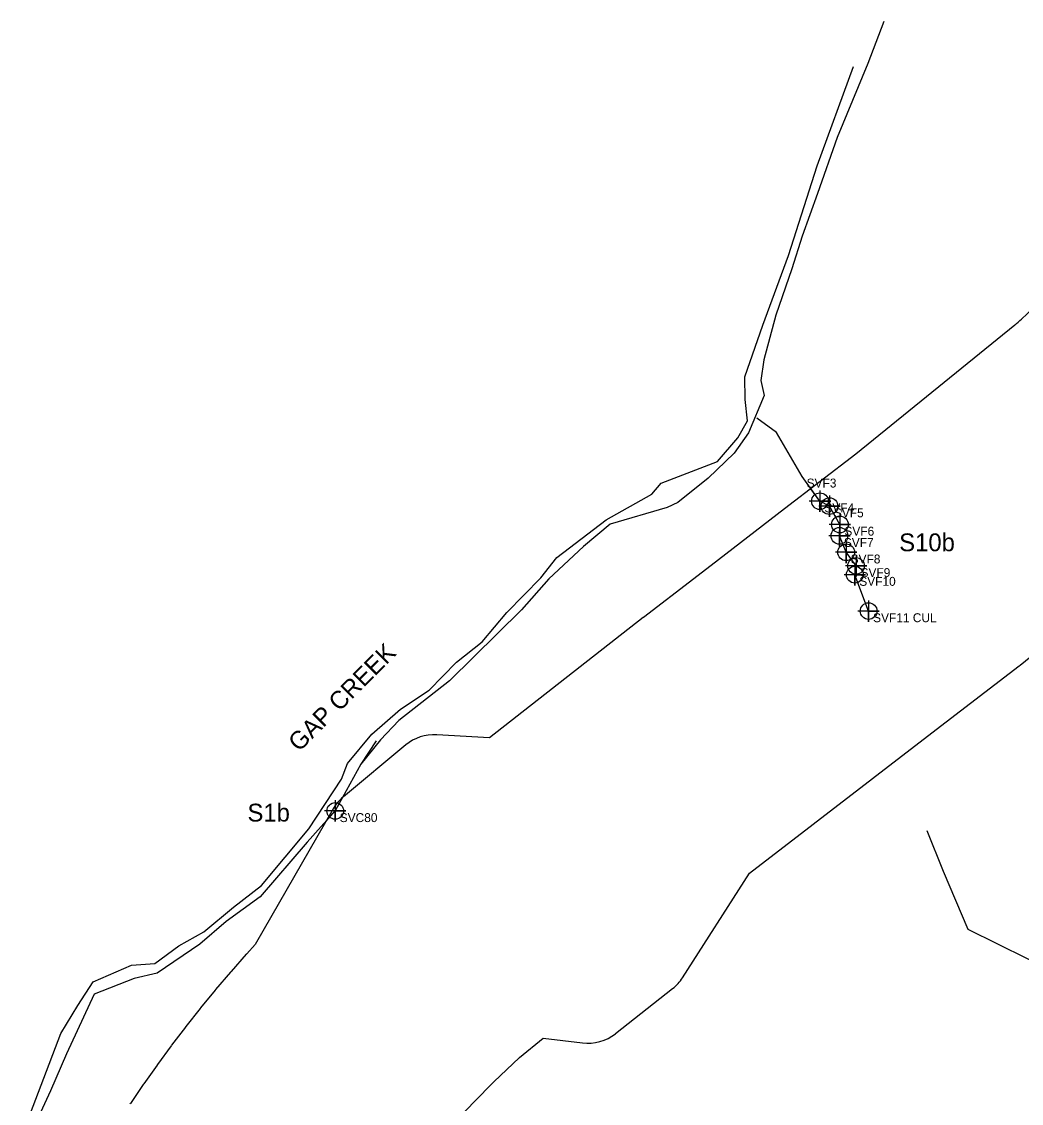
# Model space of a CAD drawing. Extents: x 1253697 to 1278588, y 912189 to 981699.
# Drawn here: x 1260127 to 1261249, y 917399 to 918613 of the extents above; entities that cross this region are included whole.
import ezdxf

# ---------------------------------------------------------------- set-up
doc = ezdxf.new("R2010")
doc.units = 0
for name, color, linetype in [('Default', 7, 'Continuous'), ('Exist Hydro Jurisdictional Stream or Body of Water Mitigable', 7, 'Continuous'), ('Exist Hydro Jurisdictional Stream or Body of Water Mitigable Cogo Comment', 7, 'Continuous'), ('Exist Hydro Jurisdictional Stream or Body of Water Mitigable Cogo Number', 7, 'Continuous'), ('Exist Hydro Jurisdictional Stream or Body of Water Mitigable Cogo Point CELL', 7, 'Continuous')]:
    doc.layers.add(name, color=color, linetype=linetype)

msp = doc.modelspace()

# ---------------------------------------------------------------- linework, layer by layer
at = {"layer": 'Default'}
for p, q in [((1260881.3, 917987.7), (1260824.7, 917944.2)), ((1260881.3, 917987.7), (1260824.7, 917944.2)), ((1260881.3, 917987.7), (1260824.7, 917944.2)), ((1260881.3, 917987.7), (1260824.7, 917944.2)), ((1260558, 917801.1), (1260488, 917743.1)), ((1260558, 917801.1), (1260488, 917743.1)), ((1260558, 917801.1), (1260488, 917743.1)), ((1260558, 917801.1), (1260488, 917743.1)), ((1260379, 917566.3), (1260362, 917547)), ((1260379, 917566.3), (1260362, 917547)), ((1260379, 917566.3), (1260362, 917547)), ((1260379, 917566.3), (1260362, 917547)), ((1260361.4, 917546.3), (1260344.7, 917526.7)), ((1260361.4, 917546.3), (1260344.7, 917526.7)), ((1260361.4, 917546.3), (1260344.7, 917526.7)), ((1260361.4, 917546.3), (1260344.7, 917526.7)), ((1260344.2, 917526), (1260327.8, 917506.1)), ((1260344.2, 917526), (1260327.8, 917506.1)), ((1260344.2, 917526), (1260327.8, 917506.1)), ((1260344.2, 917526), (1260327.8, 917506.1)), ((1260793.4, 917477.2), (1260857.5, 917527.7)), ((1260793.4, 917477.2), (1260857.5, 917527.7)), ((1260793.4, 917477.2), (1260857.5, 917527.7)), ((1260793.4, 917477.2), (1260857.5, 917527.7)), ((1260327.3, 917505.4), (1260311.3, 917485.2)), ((1260327.3, 917505.4), (1260311.3, 917485.2)), ((1260327.3, 917505.4), (1260311.3, 917485.2)), ((1260327.3, 917505.4), (1260311.3, 917485.2)), ((1260310.8, 917484.5), (1260295.2, 917464.1)), ((1260310.8, 917484.5), (1260295.2, 917464.1)), ((1260310.8, 917484.5), (1260295.2, 917464.1)), ((1260310.8, 917484.5), (1260295.2, 917464.1)), ((1260294.6, 917463.4), (1260279.4, 917442.6)), ((1260294.6, 917463.4), (1260279.4, 917442.6)), ((1260294.6, 917463.4), (1260279.4, 917442.6)), ((1260294.6, 917463.4), (1260279.4, 917442.6)), ((1260278.9, 917441.9), (1260264, 917420.9)), ((1260278.9, 917441.9), (1260264, 917420.9)), ((1260278.9, 917441.9), (1260264, 917420.9)), ((1260278.9, 917441.9), (1260264, 917420.9)), ((1260263.5, 917420.2), (1260249, 917399)), ((1260263.5, 917420.2), (1260249, 917399)), ((1260263.5, 917420.2), (1260249, 917399)), ((1260263.5, 917420.2), (1260249, 917399))]:
    msp.add_line(p, q, dxfattribs=at)
for points in [[(1261241.5, 918272.3), (1261062.9, 918127.4), (1260983, 918065.9)], [(1261241.5, 918272.3), (1261062.9, 918127.4), (1260983, 918065.9)], [(1261241.5, 918272.3), (1261062.9, 918127.4), (1260983, 918065.9)], [(1261241.5, 918272.3), (1261062.9, 918127.4), (1260983, 918065.9)], [(1260983, 918065.9), (1260909.1, 918009), (1260881.3, 917987.7)], [(1260983, 918065.9), (1260909.1, 918009), (1260881.3, 917987.7)], [(1260983, 918065.9), (1260909.1, 918009), (1260881.3, 917987.7)], [(1260983, 918065.9), (1260909.1, 918009), (1260881.3, 917987.7)], [(1261247.4, 917890.8), (1261416.8, 918028.6), (1261454.5, 918047.8)], [(1261247.4, 917890.8), (1261416.8, 918028.6), (1261454.5, 918047.8)], [(1261247.4, 917890.8), (1261416.8, 918028.6), (1261454.5, 918047.8)], [(1261247.4, 917890.8), (1261416.8, 918028.6), (1261454.5, 918047.8)], [(1260824.5, 917944), (1260651.8, 917809.3), (1260592.7, 917812.6)], [(1260824.5, 917944), (1260651.8, 917809.3), (1260592.7, 917812.6)], [(1260824.5, 917944), (1260651.8, 917809.3), (1260592.7, 917812.6)], [(1260824.5, 917944), (1260651.8, 917809.3), (1260592.7, 917812.6)], [(1260868.6, 917540), (1260943.9, 917657.4), (1261153.2, 917818.4), (1261246.4, 917890)], [(1260868.6, 917540), (1260943.9, 917657.4), (1261153.2, 917818.4), (1261246.4, 917890)], [(1260868.6, 917540), (1260943.9, 917657.4), (1261153.2, 917818.4), (1261246.4, 917890)], [(1260868.6, 917540), (1260943.9, 917657.4), (1261153.2, 917818.4), (1261246.4, 917890)], [(1260476.6, 917729.5), (1260389, 917577.3), (1260379.5, 917566.8)], [(1260476.6, 917729.5), (1260389, 917577.3), (1260379.5, 917566.8)], [(1260476.6, 917729.5), (1260389, 917577.3), (1260379.5, 917566.8)], [(1260476.6, 917729.5), (1260389, 917577.3), (1260379.5, 917566.8)], [(1260398.1, 917040.1), (1260410.1, 917077.5), (1260434.6, 917126.2), (1260458.2, 917168.4), (1260476.3, 917198.2), (1260495.7, 917228.3), (1260510.6, 917250.1), (1260521.4, 917265.3), (1260554.6, 917309.3), (1260592.2, 917354.5), (1260594.4, 917357.1), (1260608.3, 917372.7), (1260634.3, 917400.2), (1260656.8, 917423.1), (1260685.8, 917450.6), (1260712.3, 917472.2), (1260756.3, 917466.8)], [(1260398.1, 917040.1), (1260410.1, 917077.5), (1260434.6, 917126.2), (1260458.2, 917168.4), (1260476.3, 917198.2), (1260495.7, 917228.3), (1260510.6, 917250.1), (1260521.4, 917265.3), (1260554.6, 917309.3), (1260592.2, 917354.5), (1260594.4, 917357.1), (1260608.3, 917372.7), (1260634.3, 917400.2), (1260656.8, 917423.1), (1260685.8, 917450.6), (1260712.3, 917472.2), (1260756.3, 917466.8)], [(1260398.1, 917040.1), (1260410.1, 917077.5), (1260434.6, 917126.2), (1260458.2, 917168.4), (1260476.3, 917198.2), (1260495.7, 917228.3), (1260510.6, 917250.1), (1260521.4, 917265.3), (1260554.6, 917309.3), (1260592.2, 917354.5), (1260594.4, 917357.1), (1260608.3, 917372.7), (1260634.3, 917400.2), (1260656.8, 917423.1), (1260685.8, 917450.6), (1260712.3, 917472.2), (1260756.3, 917466.8)], [(1260398.1, 917040.1), (1260410.1, 917077.5), (1260434.6, 917126.2), (1260458.2, 917168.4), (1260476.3, 917198.2), (1260495.7, 917228.3), (1260510.6, 917250.1), (1260521.4, 917265.3), (1260554.6, 917309.3), (1260592.2, 917354.5), (1260594.4, 917357.1), (1260608.3, 917372.7), (1260634.3, 917400.2), (1260656.8, 917423.1), (1260685.8, 917450.6), (1260712.3, 917472.2), (1260756.3, 917466.8)]]:
    msp.add_lwpolyline(points, dxfattribs=at)
for centre, radius, start, end in [((1260334.6, 919272.3), 1350, 312.6253, 324.3503), ((1260334.6, 919272.3), 1350, 312.6253, 324.3503), ((1260334.6, 919272.3), 1350, 312.6253, 324.3503), ((1260334.6, 919272.3), 1350, 312.6253, 324.3503), ((1260334.6, 919272.3), 1350, 312.2043, 312.625), ((1260334.6, 919272.3), 1350, 312.2043, 312.625), ((1260334.6, 919272.3), 1350, 312.2043, 312.625), ((1260334.6, 919272.3), 1350, 312.2043, 312.625), ((1261013.5, 918026.2), 50, 127.5644, 127.5645), ((1261013.5, 918026.2), 50, 127.5644, 127.5645), ((1260911.8, 917948.1), 50, 127.5643, 127.5644), ((1260911.8, 917948.1), 50, 127.5643, 127.5644), ((1260855.2, 917904.5), 50, 127.5644, 127.9536), ((1260855.2, 917904.5), 50, 127.5644, 127.9536), ((1260855.2, 917904.5), 50, 127.5644, 127.9536), ((1260855.2, 917904.5), 50, 127.5644, 127.9536), ((1261215.9, 917929.6), 50, 307.5644, 309.1169), ((1261215.9, 917929.6), 50, 307.5644, 309.1169), ((1261215.9, 917929.6), 50, 307.5644, 309.1169), ((1261215.9, 917929.6), 50, 307.5644, 309.1169), ((1260589.9, 917762.6), 50, 86.8217, 129.665), ((1260589.9, 917762.6), 50, 86.8217, 129.665), ((1260589.9, 917762.6), 50, 86.8217, 129.665), ((1260589.9, 917762.6), 50, 86.8217, 129.665), ((1260519.9, 917704.6), 50, 129.665, 150.0853), ((1260519.9, 917704.6), 50, 129.665, 150.0853), ((1260519.9, 917704.6), 50, 129.665, 150.0853), ((1260519.9, 917704.6), 50, 129.665, 150.0853), ((1260416.5, 917533.2), 50, 137.7723, 138.6493), ((1260416.5, 917533.2), 50, 137.7723, 138.6493), ((1260416.5, 917533.2), 50, 137.7723, 138.6493), ((1260416.5, 917533.2), 50, 137.7723, 138.6493), ((1260399.5, 917513.9), 50, 138.6493, 139.649), ((1260399.5, 917513.9), 50, 138.6493, 139.649), ((1260399.5, 917513.9), 50, 138.6493, 139.649), ((1260399.5, 917513.9), 50, 138.6493, 139.649), ((1260826.5, 917567), 50, 308.2886, 327.2985), ((1260826.5, 917567), 50, 308.2886, 327.2985), ((1260826.5, 917567), 50, 308.2886, 327.2985), ((1260826.5, 917567), 50, 308.2886, 327.2985), ((1260382.8, 917494.3), 50, 139.649, 140.6491), ((1260382.8, 917494.3), 50, 139.649, 140.6491), ((1260382.8, 917494.3), 50, 139.649, 140.6491), ((1260382.8, 917494.3), 50, 139.649, 140.6491), ((1260366.5, 917474.4), 50, 140.6491, 141.6487), ((1260366.5, 917474.4), 50, 140.6491, 141.6487), ((1260366.5, 917474.4), 50, 140.6491, 141.6487), ((1260366.5, 917474.4), 50, 140.6491, 141.6487), ((1260350.5, 917454.2), 50, 141.6487, 142.6489), ((1260350.5, 917454.2), 50, 141.6487, 142.6489), ((1260350.5, 917454.2), 50, 141.6487, 142.6489), ((1260350.5, 917454.2), 50, 141.6487, 142.6489), ((1260762.4, 917516.4), 50, 262.9683, 308.2886), ((1260762.4, 917516.4), 50, 262.9683, 308.2886), ((1260762.4, 917516.4), 50, 262.9683, 308.2886), ((1260762.4, 917516.4), 50, 262.9683, 308.2886), ((1260334.9, 917433.7), 50, 142.6489, 143.6488), ((1260334.9, 917433.7), 50, 142.6489, 143.6488), ((1260334.9, 917433.7), 50, 142.6489, 143.6488), ((1260334.9, 917433.7), 50, 142.6489, 143.6488), ((1260319.7, 917413), 50, 143.6488, 144.6498), ((1260319.7, 917413), 50, 143.6488, 144.6498), ((1260319.7, 917413), 50, 143.6488, 144.6498), ((1260319.7, 917413), 50, 143.6488, 144.6498), ((1260304.8, 917392), 50, 144.6498, 145.6485), ((1260304.8, 917392), 50, 144.6498, 145.6485), ((1260304.8, 917392), 50, 144.6498, 145.6485), ((1260304.8, 917392), 50, 144.6498, 145.6485), ((1260290.2, 917370.8), 50, 145.6485, 146.6496), ((1260290.2, 917370.8), 50, 145.6485, 146.6496), ((1260290.2, 917370.8), 50, 145.6485, 146.6496), ((1260290.2, 917370.8), 50, 145.6485, 146.6496)]:
    msp.add_arc(centre, radius, start, end, dxfattribs=at)
at = {"layer": 'Exist Hydro Jurisdictional Stream or Body of Water Mitigable'}
for points in [[(1261094.4, 918612.8), (1261076.4, 918565.6), (1261042, 918482.7), (1261020.2, 918419.9), (1261003, 918372.1), (1260991.1, 918335.3), (1260973.4, 918283.3), (1260959.9, 918233.3), (1260956.3, 918209.9), (1260960.3, 918193.2), (1260942.5, 918151.4), (1260926.5, 918128.7), (1260897.4, 918100.6), (1260863.3, 918073.1), (1260851.5, 918067.4), (1260787.4, 918048.8), (1260757.4, 918024), (1260718.5, 917987.7), (1260688, 917952.8), (1260607, 917873), (1260550.2, 917828.4), (1260529.5, 917806.8), (1260507.7, 917779.4), (1260478.9, 917727.1)], [(1260519.9, 917813.1), (1260552.2, 917841.2), (1260584.3, 917862.6), (1260614.8, 917893.9), (1260643.7, 917917), (1260671.4, 917949.6), (1260709.6, 917988.6), (1260727.7, 918011.5), (1260782.9, 918053.7), (1260834, 918082.6), (1260844.7, 918094.8), (1260907.7, 918119.2), (1260930.6, 918145.8), (1260941.5, 918165), (1260938.7, 918188.7), (1260938.5, 918214.1), (1260958.5, 918272.2), (1260987.4, 918350.3), (1261019.6, 918451), (1261060.6, 918562.4)], [(1261022.8, 918074.6), (1261002.8, 918102.5), (1260973.9, 918151.6), (1260951.8, 918168)], [(1261077.4, 917951.4), (1261061.9, 917992.2), (1261063.3, 918002), (1261052.2, 918017.3), (1261044.6, 918035.8), (1261045.2, 918048.5), (1261033.4, 918069.1), (1261022.8, 918074.6), (1261012.7, 918088.7)], [(1260127, 917361.6), (1260170.9, 917477.3), (1260190.2, 917508.9), (1260207.4, 917535.4), (1260250.2, 917554), (1260276.4, 917555.8), (1260303.2, 917575.8), (1260331.6, 917591.3), (1260364.6, 917619.1), (1260396.1, 917643.4), (1260449.1, 917707), (1260485.9, 917762.6), (1260492.7, 917780.4), (1260519.9, 917813.1), (1260552.2, 917841.2)], [(1260524.9, 917805.6), (1260507.7, 917779.4), (1260478.9, 917727.1), (1260447.4, 917692.1), (1260394.6, 917630.8), (1260356.5, 917603), (1260326.9, 917577.6), (1260279.2, 917545.1), (1260253.3, 917538.9), (1260208.3, 917521.6), (1260177.3, 917454.4), (1260159.2, 917413.2), (1260132, 917354.1)], [(1260468.6, 917715.7), (1260478.9, 917727.1), (1260487.4, 917742.6)], [(1261142.6, 917705), (1261161.2, 917659.5), (1261188.8, 917594.5), (1261255.2, 917561.5), (1261275, 917551.7), (1261305.9, 917499.5), (1261331.1, 917466.4), (1261342.7, 917455.4), (1261364, 917459.9)]]:
    msp.add_lwpolyline(points, dxfattribs=at)
at = {"layer": 'Exist Hydro Jurisdictional Stream or Body of Water Mitigable Cogo Point CELL'}
for points in [[(1261022.8, 918086.6), (1261022.8, 918062.6), (1261022.8, 918074.6), (1261034.8, 918074.6), (1261010.8, 918074.6)], [(1261033.4, 918081.1), (1261033.4, 918057.1), (1261033.4, 918069.1), (1261045.4, 918069.1), (1261021.4, 918069.1)], [(1261045.2, 918060.5), (1261045.2, 918036.5), (1261045.2, 918048.5), (1261057.2, 918048.5), (1261033.2, 918048.5)], [(1261044.6, 918047.8), (1261044.6, 918023.8), (1261044.6, 918035.8), (1261056.6, 918035.8), (1261032.6, 918035.8)], [(1261052.2, 918029.3), (1261052.2, 918005.3), (1261052.2, 918017.3), (1261064.2, 918017.3), (1261040.2, 918017.3)], [(1261063.3, 918014), (1261063.3, 917990), (1261063.3, 918002), (1261075.3, 918002), (1261051.3, 918002)], [(1261061.9, 918004.2), (1261061.9, 917980.2), (1261061.9, 917992.2), (1261073.9, 917992.2), (1261049.9, 917992.2)], [(1261077.4, 917963.4), (1261077.4, 917939.4), (1261077.4, 917951.4), (1261089.4, 917951.4), (1261065.4, 917951.4)], [(1260478.9, 917739.1), (1260478.9, 917715.1), (1260478.9, 917727.1), (1260490.9, 917727.1), (1260466.9, 917727.1)]]:
    msp.add_lwpolyline(points, dxfattribs=at)
for centre in [(1261022.8, 918074.6), (1261033.4, 918069.1), (1261045.2, 918048.5), (1261044.6, 918035.8), (1261052.2, 918017.3), (1261063.3, 918002), (1261061.9, 917992.2), (1261077.4, 917951.4), (1260478.9, 917727.1)]:
    msp.add_circle(centre, 9.38, dxfattribs=at)

# ---------------------------------------------------------------- texts
at = {"layer": 'Exist Hydro Jurisdictional Stream or Body of Water Mitigable Cogo Comment'}
for s, p in [('SVF3', (1261007.8, 918090)), ('SVF4', (1261027.8, 918062.1)), ('SVF5', (1261038.4, 918056.6)), ('SVF6', (1261050.2, 918036)), ('SVF7', (1261049.6, 918023.3)), ('SVF8', (1261057.2, 918004.8)), ('SVF9', (1261068.3, 917989.5)), ('SVF10', (1261066.9, 917979.7)), ('SVF11 CUL', (1261082.4, 917938.9)), ('SVC80', (1260483.9, 917714.6))]:
    msp.add_text(s, height=10, dxfattribs=at).set_placement(p)
at = {"layer": 'Exist Hydro Jurisdictional Stream or Body of Water Mitigable Cogo Number'}
for s, p in [('S10b', (1261111.7, 918018.5)), ('S1b', (1260380.4, 917715.2))]:
    msp.add_text(s, height=20, dxfattribs=at).set_placement(p)
msp.add_text('GAP CREEK', height=20, rotation=45, dxfattribs=at).set_placement((1260438.3, 917792.6))

doc.saveas('drawing.dxf')
